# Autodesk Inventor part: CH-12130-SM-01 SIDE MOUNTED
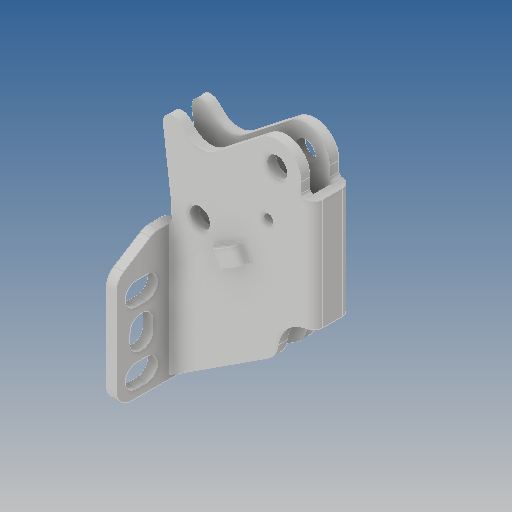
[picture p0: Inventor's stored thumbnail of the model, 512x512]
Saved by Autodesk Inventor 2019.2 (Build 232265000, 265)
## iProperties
Created: 2012-09
Part Number: CH-12130-SM-01 SIDE MOUNTED
Material: Ogólny
Document SubType Name: Modeling
Designer: CADENGINEERING4
Density: 1 g/cm^3
Appearance: Domyślna
Author: CADENGINEERING4
Revision Number: ÈÎºÎ
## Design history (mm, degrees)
feature "Ô²½Ç19"
node "Bryła1"
